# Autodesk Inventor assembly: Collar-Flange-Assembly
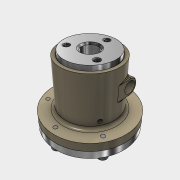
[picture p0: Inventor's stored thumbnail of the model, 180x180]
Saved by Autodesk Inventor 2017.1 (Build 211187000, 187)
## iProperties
Shininess: 64.0
Length Units: 11269
Angle Units: 11279
Time Units: 11290
Mass Units: 11283
Length Display Precision: 3
Angle Display Precision: 2
Compacted: True
Created: 2004-01
Part Number: Collar-Flange-Assembly
Document SubType Name: Assembly
Designer: Administrator
Manufacturer: Standard
Standards Organization: Custom
Density: 0.0
Volumn: 0.0
Area: 0.0
PropertySet Name: Model Information
Control State: 0
Master: False
Checked Out: False
Author: Administrator
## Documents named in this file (6)
- C:\Users\Brian\Documents\Inventor\Collar-Flange-Drawings\Collar-Flange-Assembly.iam
- C:\Users\Brian\Documents\Inventor\Collar-Flange-Drawings\Flanged-Collar.ipt
- C:\Users\Brian\Documents\Inventor\Collar-Flange-Drawings\Copper-Gasket.ipt
- C:\Users\Brian\Documents\Inventor\Collar-Flange-Drawings\Collar-Insert.ipt
- C:\Users\Brian\Documents\Inventor\Collar-Flange-Drawings\Collar-End-Cap.ipt
- C:\Users\Brian\Documents\Inventor\Collar-Flange-Drawings\local.AFNOR.19.400.8.ipt
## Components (8 placed, 5 different names)
1. Flanged-Collar:1 — Mate:2, Insert:1, Insert:7, Insert:8, Mate:3
2. Copper-Gasket:1 — Flush:1, Insert:1
3. Collar-Insert:1 — Flush:2, Mate:2, Mate:3
4. Collar-End-Cap:1 — Insert:3, Insert:4, Insert:5, Insert:6, Insert:7, Insert:8
5. NF E 25-125  (Regular Thread) M3 x 10:1 — Insert:3
6. NF E 25-125  (Regular Thread) M3 x 10:2 — Insert:4
7. NF E 25-125  (Regular Thread) M3 x 10:3 — Insert:5
8. NF E 25-125  (Regular Thread) M3 x 10:4 — Insert:6
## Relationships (11: Insert 7, Flush 2, Mate 2)
- Flush:1: Copper-Gasket:1
- Flush:2: Collar-Insert:1
- Mate:2: Flanged-Collar:1 ↔ Collar-Insert:1
- Insert:1: Flanged-Collar:1 ↔ Copper-Gasket:1
- Insert:3: Collar-End-Cap:1 ↔ NF E 25-125  (Regular Thread) M3 x 10:1
- Insert:4: Collar-End-Cap:1 ↔ NF E 25-125  (Regular Thread) M3 x 10:2
- Insert:5: Collar-End-Cap:1 ↔ NF E 25-125  (Regular Thread) M3 x 10:3
- Insert:6: Collar-End-Cap:1 ↔ NF E 25-125  (Regular Thread) M3 x 10:4
- Insert:7: Flanged-Collar:1 ↔ Collar-End-Cap:1
- Insert:8: Flanged-Collar:1 ↔ Collar-End-Cap:1
- Mate:3: Flanged-Collar:1 ↔ Collar-Insert:1
